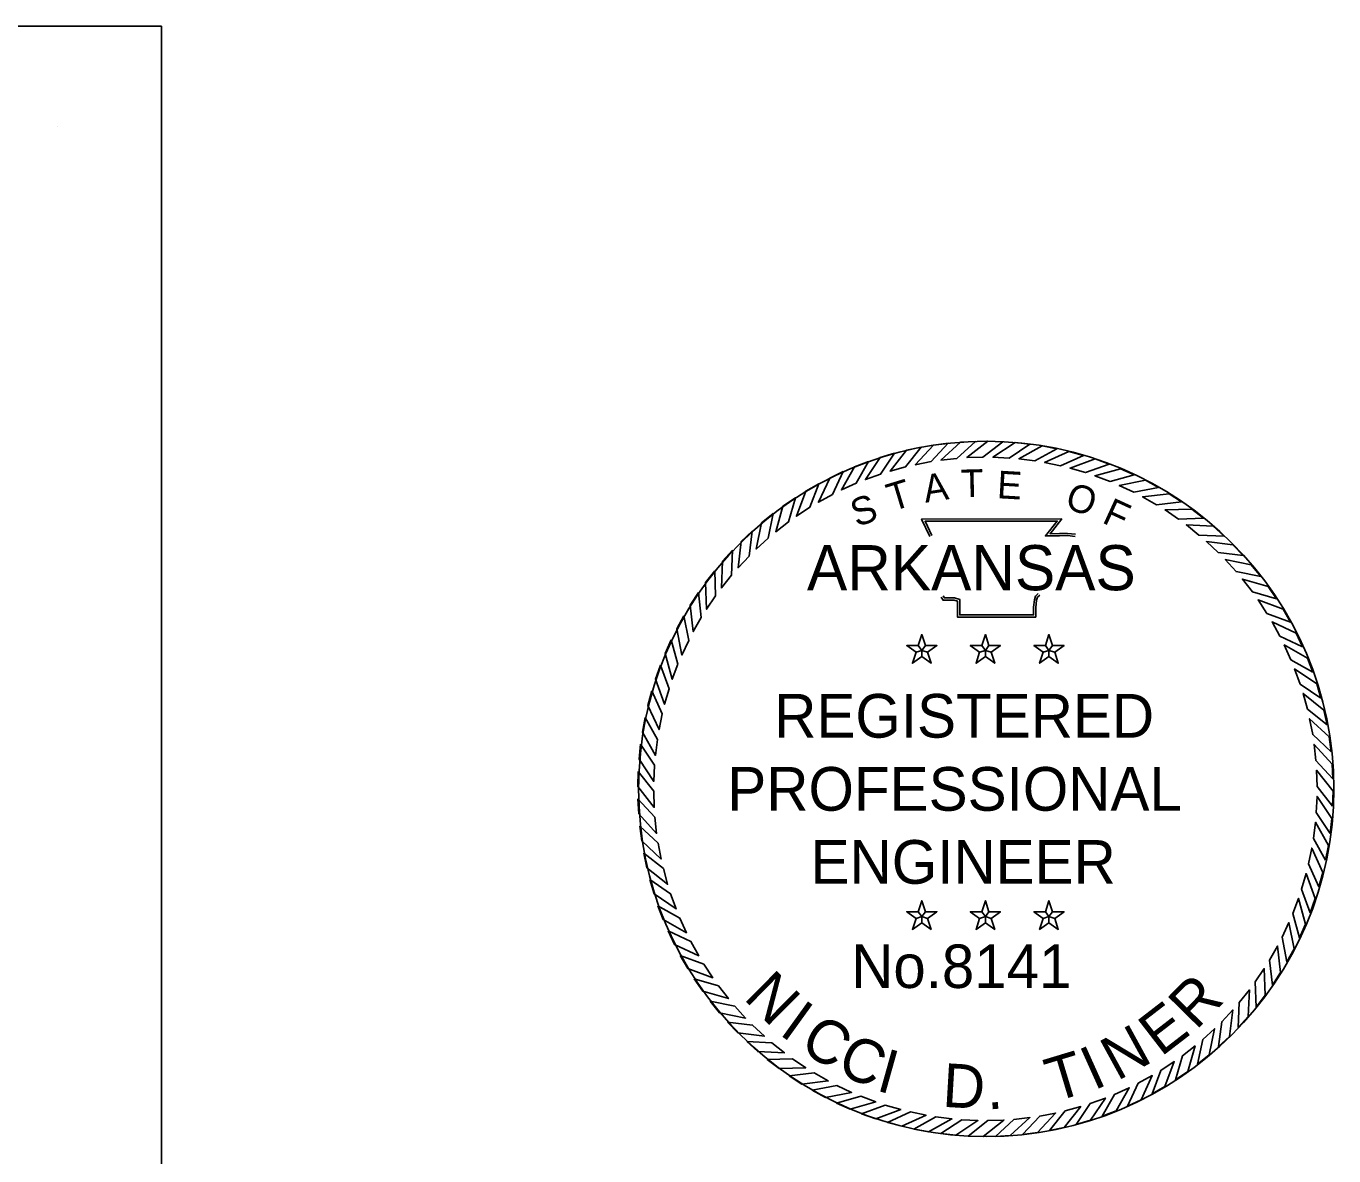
# Model space of a CAD drawing. Extents: x 0 to 19, y -0.6 to 11.2.
# Drawn here: x 16.766 to 19.023, y 9.05 to 11 of the extents above; entities that cross this region are included whole.
import ezdxf

# ---------------------------------------------------------------- set-up
doc = ezdxf.new("R2010")
doc.units = 0
for name, color, linetype in [('G-ANNO-SYMB', 7, 'Continuous'), ('G-ANNO-TEXT', 7, 'Continuous'), ('G-Border-Paper', 7, 'Continuous'), ('G-No Plot-Stamp-1', 7, 'Continuous')]:
    doc.layers.add(name, color=color, linetype=linetype)

msp = doc.modelspace()

# ---------------------------------------------------------------- linework, layer by layer
at = {"layer": 'G-ANNO-SYMB'}
for points in [[(18.3112, 10.2732), (18.2859, 10.2679), (18.2573, 10.2319), (18.2842, 10.2393)], [(18.3578, 10.2801), (18.3322, 10.2768), (18.3008, 10.2431), (18.3282, 10.2484)], [(18.4048, 10.2833), (18.379, 10.282), (18.3451, 10.2509), (18.3728, 10.254)], [(18.4519, 10.2828), (18.4261, 10.2835), (18.3899, 10.2552), (18.4177, 10.2561)], [(18.4988, 10.2786), (18.4732, 10.2813), (18.4348, 10.256), (18.4627, 10.2546)], [(18.5453, 10.2707), (18.5199, 10.2755), (18.4797, 10.2532), (18.5073, 10.2497)], [(18.2203, 10.2486), (18.1962, 10.2394), (18.1735, 10.1994), (18.1989, 10.2109)], [(18.2652, 10.2627), (18.2405, 10.2554), (18.2148, 10.2173), (18.241, 10.2268)], [(18.591, 10.2592), (18.5661, 10.266), (18.5242, 10.2469), (18.5515, 10.2412)], [(18.6356, 10.2442), (18.6113, 10.2529), (18.5681, 10.2371), (18.5949, 10.2294)], [(18.1766, 10.2311), (18.1533, 10.22), (18.1338, 10.1783), (18.1582, 10.1918)], [(18.6789, 10.2257), (18.6554, 10.2362), (18.6111, 10.224), (18.6372, 10.2141)], [(18.1344, 10.2101), (18.112, 10.1973), (18.0959, 10.1542), (18.1192, 10.1695)], [(18.7207, 10.2039), (18.698, 10.2162), (18.6529, 10.2074), (18.6781, 10.1956)], [(18.0939, 10.1859), (18.0726, 10.1714), (18.06, 10.1272), (18.082, 10.1443)], [(18.7606, 10.1788), (18.739, 10.1929), (18.6933, 10.1877), (18.7175, 10.1739)], [(18.0555, 10.1587), (18.0354, 10.1425), (18.0263, 10.0974), (18.0469, 10.1162)], [(18.7984, 10.1507), (18.778, 10.1665), (18.732, 10.1649), (18.7551, 10.1492)], [(18.8339, 10.1197), (18.8148, 10.137), (18.7688, 10.1391), (18.7906, 10.1216)], [(18.0194, 10.1284), (18.0006, 10.1107), (17.995, 10.0651), (18.0141, 10.0854)], [(17.9857, 10.0955), (17.9684, 10.0764), (17.9664, 10.0304), (17.9838, 10.0522)], [(18.8669, 10.0861), (18.8491, 10.1048), (18.8035, 10.1104), (18.8238, 10.0914)], [(18.8971, 10.0499), (18.8809, 10.07), (18.8358, 10.0792), (18.8546, 10.0586)], [(17.9547, 10.06), (17.939, 10.0396), (17.9406, 9.9936), (17.9562, 10.0167)], [(18.9244, 10.0115), (18.9098, 10.0328), (18.8656, 10.0455), (18.8827, 10.0235)], [(17.9266, 10.0222), (17.9125, 10.0006), (17.9177, 9.9549), (17.9315, 9.9791)], [(18.9485, 9.9711), (18.9357, 9.9935), (18.8926, 10.0096), (18.9079, 9.9863)], [(17.9016, 9.9823), (17.8892, 9.9596), (17.898, 9.9145), (17.9099, 9.9397)], [(18.9695, 9.9289), (18.9584, 9.9522), (18.9167, 9.9716), (18.9302, 9.9472)], [(17.8798, 9.9405), (17.8692, 9.917), (17.8815, 9.8727), (17.8913, 9.8987)], [(18.3122, 9.9224), (18.3184, 9.9309), (18.3122, 9.9499), (18.3061, 9.9309)], [(18.4219, 9.9224), (18.4281, 9.9309), (18.4219, 9.9499), (18.4158, 9.9309)], [(18.5317, 9.9224), (18.5378, 9.9309), (18.5317, 9.9499), (18.5255, 9.9309)], [(18.987, 9.8852), (18.9779, 9.9093), (18.9378, 9.9319), (18.9493, 9.9065)], [(18.3122, 9.9224), (18.3061, 9.9309), (18.2861, 9.9309), (18.3023, 9.9192)], [(18.3122, 9.9224), (18.3023, 9.9192), (18.2961, 9.9003), (18.3122, 9.912)], [(18.3122, 9.9224), (18.3222, 9.9192), (18.3383, 9.9309), (18.3184, 9.9309)], [(18.3122, 9.9224), (18.3122, 9.912), (18.3283, 9.9003), (18.3222, 9.9192)], [(18.4219, 9.9224), (18.4158, 9.9309), (18.3958, 9.9309), (18.412, 9.9192)], [(18.4219, 9.9224), (18.412, 9.9192), (18.4058, 9.9003), (18.4219, 9.912)], [(18.4219, 9.9224), (18.4319, 9.9192), (18.448, 9.9309), (18.4281, 9.9309)], [(18.4219, 9.9224), (18.4219, 9.912), (18.4381, 9.9003), (18.4319, 9.9192)], [(18.5317, 9.9224), (18.5255, 9.9309), (18.5056, 9.9309), (18.5217, 9.9192)], [(18.5317, 9.9224), (18.5217, 9.9192), (18.5155, 9.9003), (18.5317, 9.912)], [(18.5317, 9.9224), (18.5416, 9.9192), (18.5577, 9.9309), (18.5378, 9.9309)], [(18.5317, 9.9224), (18.5317, 9.912), (18.5478, 9.9003), (18.5416, 9.9192)], [(17.8613, 9.8972), (17.8526, 9.8729), (17.8683, 9.8297), (17.8761, 9.8564)], [(19.0011, 9.8402), (18.9939, 9.865), (18.9557, 9.8907), (18.9652, 9.8645)], [(17.8462, 9.8525), (17.8395, 9.8276), (17.8586, 9.7858), (17.8642, 9.8131)], [(19.0116, 9.7943), (19.0063, 9.8195), (18.9703, 9.8482), (18.9777, 9.8213)], [(17.8347, 9.8069), (17.83, 9.7815), (17.8523, 9.7413), (17.8558, 9.7689)], [(19.0185, 9.7477), (19.0152, 9.7733), (18.9816, 9.8046), (18.9868, 9.7772)], [(17.8269, 9.7604), (17.8241, 9.7347), (17.8495, 9.6964), (17.8508, 9.7242)], [(19.0217, 9.7007), (19.0204, 9.7264), (18.9893, 9.7603), (18.9924, 9.7326)], [(17.8227, 9.7135), (17.8219, 9.6877), (17.8503, 9.6514), (17.8494, 9.6793)], [(19.0212, 9.6536), (19.0219, 9.6793), (18.9936, 9.7156), (18.9945, 9.6877)], [(17.8222, 9.6664), (17.8235, 9.6406), (17.8545, 9.6067), (17.8515, 9.6344)], [(19.017, 9.6066), (19.0198, 9.6323), (18.9944, 9.6706), (18.9931, 9.6428)], [(17.8254, 9.6194), (17.8287, 9.5938), (17.8623, 9.5624), (17.8571, 9.5898)], [(19.0091, 9.5602), (19.0139, 9.5855), (18.9916, 9.6258), (18.9881, 9.5981)], [(17.8322, 9.5728), (17.8375, 9.5475), (17.8735, 9.5189), (17.8662, 9.5458)], [(18.9976, 9.5145), (19.0044, 9.5394), (18.9853, 9.5812), (18.9797, 9.5539)], [(17.8427, 9.5268), (17.85, 9.5021), (17.8881, 9.4764), (17.8787, 9.5026)], [(18.9826, 9.4698), (18.9913, 9.4941), (18.9755, 9.5374), (18.9678, 9.5106)], [(17.8568, 9.4819), (17.866, 9.4578), (17.906, 9.4351), (17.8946, 9.4605)], [(18.3122, 9.463), (18.3184, 9.4715), (18.3122, 9.4904), (18.3061, 9.4715)], [(18.4219, 9.463), (18.4281, 9.4715), (18.4219, 9.4904), (18.4158, 9.4715)], [(18.5317, 9.463), (18.5378, 9.4715), (18.5317, 9.4904), (18.5255, 9.4715)], [(18.9641, 9.4265), (18.9747, 9.4501), (18.9624, 9.4944), (18.9525, 9.4683)], [(18.3122, 9.463), (18.3061, 9.4715), (18.2861, 9.4715), (18.3023, 9.4598)], [(18.3122, 9.463), (18.3023, 9.4598), (18.2961, 9.4408), (18.3122, 9.4525)], [(18.3122, 9.463), (18.3222, 9.4598), (18.3383, 9.4715), (18.3184, 9.4715)], [(18.3122, 9.463), (18.3122, 9.4525), (18.3283, 9.4408), (18.3222, 9.4598)], [(18.4219, 9.463), (18.4158, 9.4715), (18.3958, 9.4715), (18.412, 9.4598)], [(18.4219, 9.463), (18.412, 9.4598), (18.4058, 9.4408), (18.4219, 9.4525)], [(18.4219, 9.463), (18.4319, 9.4598), (18.448, 9.4715), (18.4281, 9.4715)], [(18.4219, 9.463), (18.4219, 9.4525), (18.4381, 9.4408), (18.4319, 9.4598)], [(18.5317, 9.463), (18.5255, 9.4715), (18.5056, 9.4715), (18.5217, 9.4598)], [(18.5317, 9.463), (18.5217, 9.4598), (18.5155, 9.4408), (18.5317, 9.4525)], [(18.5317, 9.463), (18.5416, 9.4598), (18.5577, 9.4715), (18.5378, 9.4715)], [(18.5317, 9.463), (18.5317, 9.4525), (18.5478, 9.4408), (18.5416, 9.4598)], [(17.8744, 9.4382), (17.8854, 9.4148), (17.9271, 9.3954), (17.9137, 9.4198)], [(18.9423, 9.3848), (18.9546, 9.4074), (18.9459, 9.4526), (18.934, 9.4273)], [(18.9172, 9.3449), (18.9313, 9.3665), (18.9261, 9.4122), (18.9123, 9.3879)], [(17.8953, 9.3959), (17.9082, 9.3736), (17.9513, 9.3575), (17.9359, 9.3808)], [(18.8891, 9.307), (18.9049, 9.3275), (18.9033, 9.3734), (18.8876, 9.3504)], [(17.9195, 9.3555), (17.9341, 9.3342), (17.9783, 9.3215), (17.9612, 9.3436)], [(18.8582, 9.2715), (18.8755, 9.2907), (18.8775, 9.3366), (18.8601, 9.3149)], [(17.9468, 9.3171), (17.963, 9.297), (18.0081, 9.2879), (17.9893, 9.3085)], [(18.8245, 9.2386), (18.8432, 9.2563), (18.8489, 9.302), (18.8298, 9.2816)], [(17.977, 9.281), (17.9947, 9.2622), (18.0404, 9.2566), (18.02, 9.2757)], [(18.7883, 9.2084), (18.8084, 9.2246), (18.8176, 9.2696), (18.797, 9.2509)], [(18.01, 9.2473), (18.0291, 9.23), (18.075, 9.228), (18.0533, 9.2454)], [(18.7499, 9.1811), (18.7712, 9.1957), (18.7839, 9.2399), (18.7619, 9.2228)], [(18.0455, 9.2163), (18.0659, 9.2006), (18.1119, 9.2022), (18.0888, 9.2178)], [(18.7095, 9.1569), (18.7319, 9.1698), (18.748, 9.2128), (18.7247, 9.1975)], [(18.0833, 9.1882), (18.1049, 9.1741), (18.1506, 9.1793), (18.1264, 9.1931)], [(18.6673, 9.136), (18.6906, 9.147), (18.71, 9.1887), (18.6856, 9.1753)], [(18.1232, 9.1632), (18.1458, 9.1508), (18.191, 9.1596), (18.1657, 9.1714)], [(18.6236, 9.1184), (18.6477, 9.1276), (18.6703, 9.1676), (18.6449, 9.1561)], [(18.1649, 9.1413), (18.1885, 9.1308), (18.2328, 9.1431), (18.2067, 9.1529)], [(18.5786, 9.1043), (18.6034, 9.1116), (18.6291, 9.1497), (18.6029, 9.1403)], [(18.2083, 9.1228), (18.2326, 9.1142), (18.2758, 9.1299), (18.249, 9.1377)], [(18.2529, 9.1078), (18.2778, 9.1011), (18.3197, 9.1201), (18.2924, 9.1258)], [(18.4861, 9.0869), (18.5117, 9.0903), (18.543, 9.1239), (18.5157, 9.1187)], [(18.5327, 9.0938), (18.5579, 9.0991), (18.5866, 9.1351), (18.5597, 9.1278)], [(18.2986, 9.0963), (18.324, 9.0916), (18.3642, 9.1139), (18.3365, 9.1173)], [(18.345, 9.0885), (18.3707, 9.0857), (18.4091, 9.1111), (18.3812, 9.1124)], [(18.392, 9.0843), (18.4178, 9.0835), (18.454, 9.1118), (18.4261, 9.1109)], [(18.4391, 9.0837), (18.4649, 9.085), (18.4988, 9.1161), (18.4711, 9.113)]]:
    msp.add_lwpolyline(points, close=True, dxfattribs=at)
for points in [[(18.3258, 10.119), (18.3118, 10.1493), (18.5538, 10.1494), (18.5336, 10.124), (18.5501, 10.1242), (18.5638, 10.1244), (18.5775, 10.1229)], [(18.3293, 10.1206), (18.3178, 10.1455), (18.5459, 10.1456), (18.5256, 10.1201), (18.5501, 10.1204), (18.5636, 10.1206), (18.5771, 10.1191)], [(18.5157, 10.0176), (18.5116, 10.0142), (18.5102, 10.0092), (18.5088, 9.9966), (18.5088, 9.9799), (18.3737, 9.9799), (18.3737, 10.0025), (18.3737, 10.0075), (18.3683, 10.0092), (18.349, 10.0092), (18.3456, 10.0144)], [(18.5133, 10.0205), (18.5082, 10.0164), (18.5064, 10.0099), (18.505, 9.9969), (18.505, 9.9838), (18.3776, 9.9838), (18.3776, 10.0025), (18.3776, 10.0104), (18.3688, 10.013), (18.3511, 10.013), (18.3488, 10.0165)]]:
    msp.add_lwpolyline(points, dxfattribs=at)
at = {"layer": 'G-ANNO-TEXT'}
msp.add_line((16.821, 10.8269), (16.821, 10.8269), dxfattribs=at)
at = {"layer": 'G-Border-Paper'}
msp.add_lwpolyline([(17, 11), (0, 11), (0, 0), (17, 0)], close=True, dxfattribs=at)
at = {"layer": 'G-No Plot-Stamp-1'}
msp.add_circle((18.4233, 9.6835), 0.6, dxfattribs=at)

# ---------------------------------------------------------------- texts
at = {"layer": 'G-ANNO-TEXT'}
for s, height, rotation, p in [('A', 0.0477, 8.6788, (18.3184, 10.1773)), ('T', 0.0477, 1.4789, (18.3801, 10.1868)), ('E', 0.0477, 356.672, (18.4412, 10.1853)), ('T', 0.0477, 16.9015, (18.2605, 10.1621)), ('O', 0.0477, 341.2218, (18.5571, 10.1689)), ('S', 0.0477, 19.7726, (18.1998, 10.1349)), ('F', 0.0477, 335.3628, (18.6214, 10.1438)), ('N', 0.0754, 315.2676, (18.0028, 9.3216)), ('R', 0.0754, 45.478, (18.7853, 9.2657)), ('I', 0.0754, 324.2141, (18.0641, 9.2609)), ('E', 0.0754, 37.6498, (18.725, 9.2201)), ('C', 0.0754, 328.6873, (18.0982, 9.2342)), ('C', 0.0754, 336.5155, (18.1624, 9.1943)), ('N', 0.0754, 28.7033, (18.6493, 9.1786)), ('I', 0.0754, 344.3437, (18.2314, 9.1635)), ('T', 0.0754, 16.7747, (18.54, 9.1425)), ('I', 0.0754, 24.2301, (18.6092, 9.1624)), ('D', 0.0754, 356.6451, (18.3466, 9.1349)), ('.', 0.0754, 4.846, (18.4256, 9.1298))]:
    msp.add_text(s, height=height, rotation=rotation, dxfattribs=at).set_placement(p)
for s, height, p in [('ARKANSAS', 0.07791, (18.114, 10.0263)), ('REGISTERED', 0.07543, (18.0574, 9.7719)), ('PROFESSIONAL', 0.07543, (17.9765, 9.6458)), ('ENGINEER', 0.07543, (18.1202, 9.5197)), ('No.8141', 0.07513, (18.1905, 9.3398))]:
    msp.add_text(s, height=height, dxfattribs=at).set_placement(p)

doc.saveas('drawing.dxf')
